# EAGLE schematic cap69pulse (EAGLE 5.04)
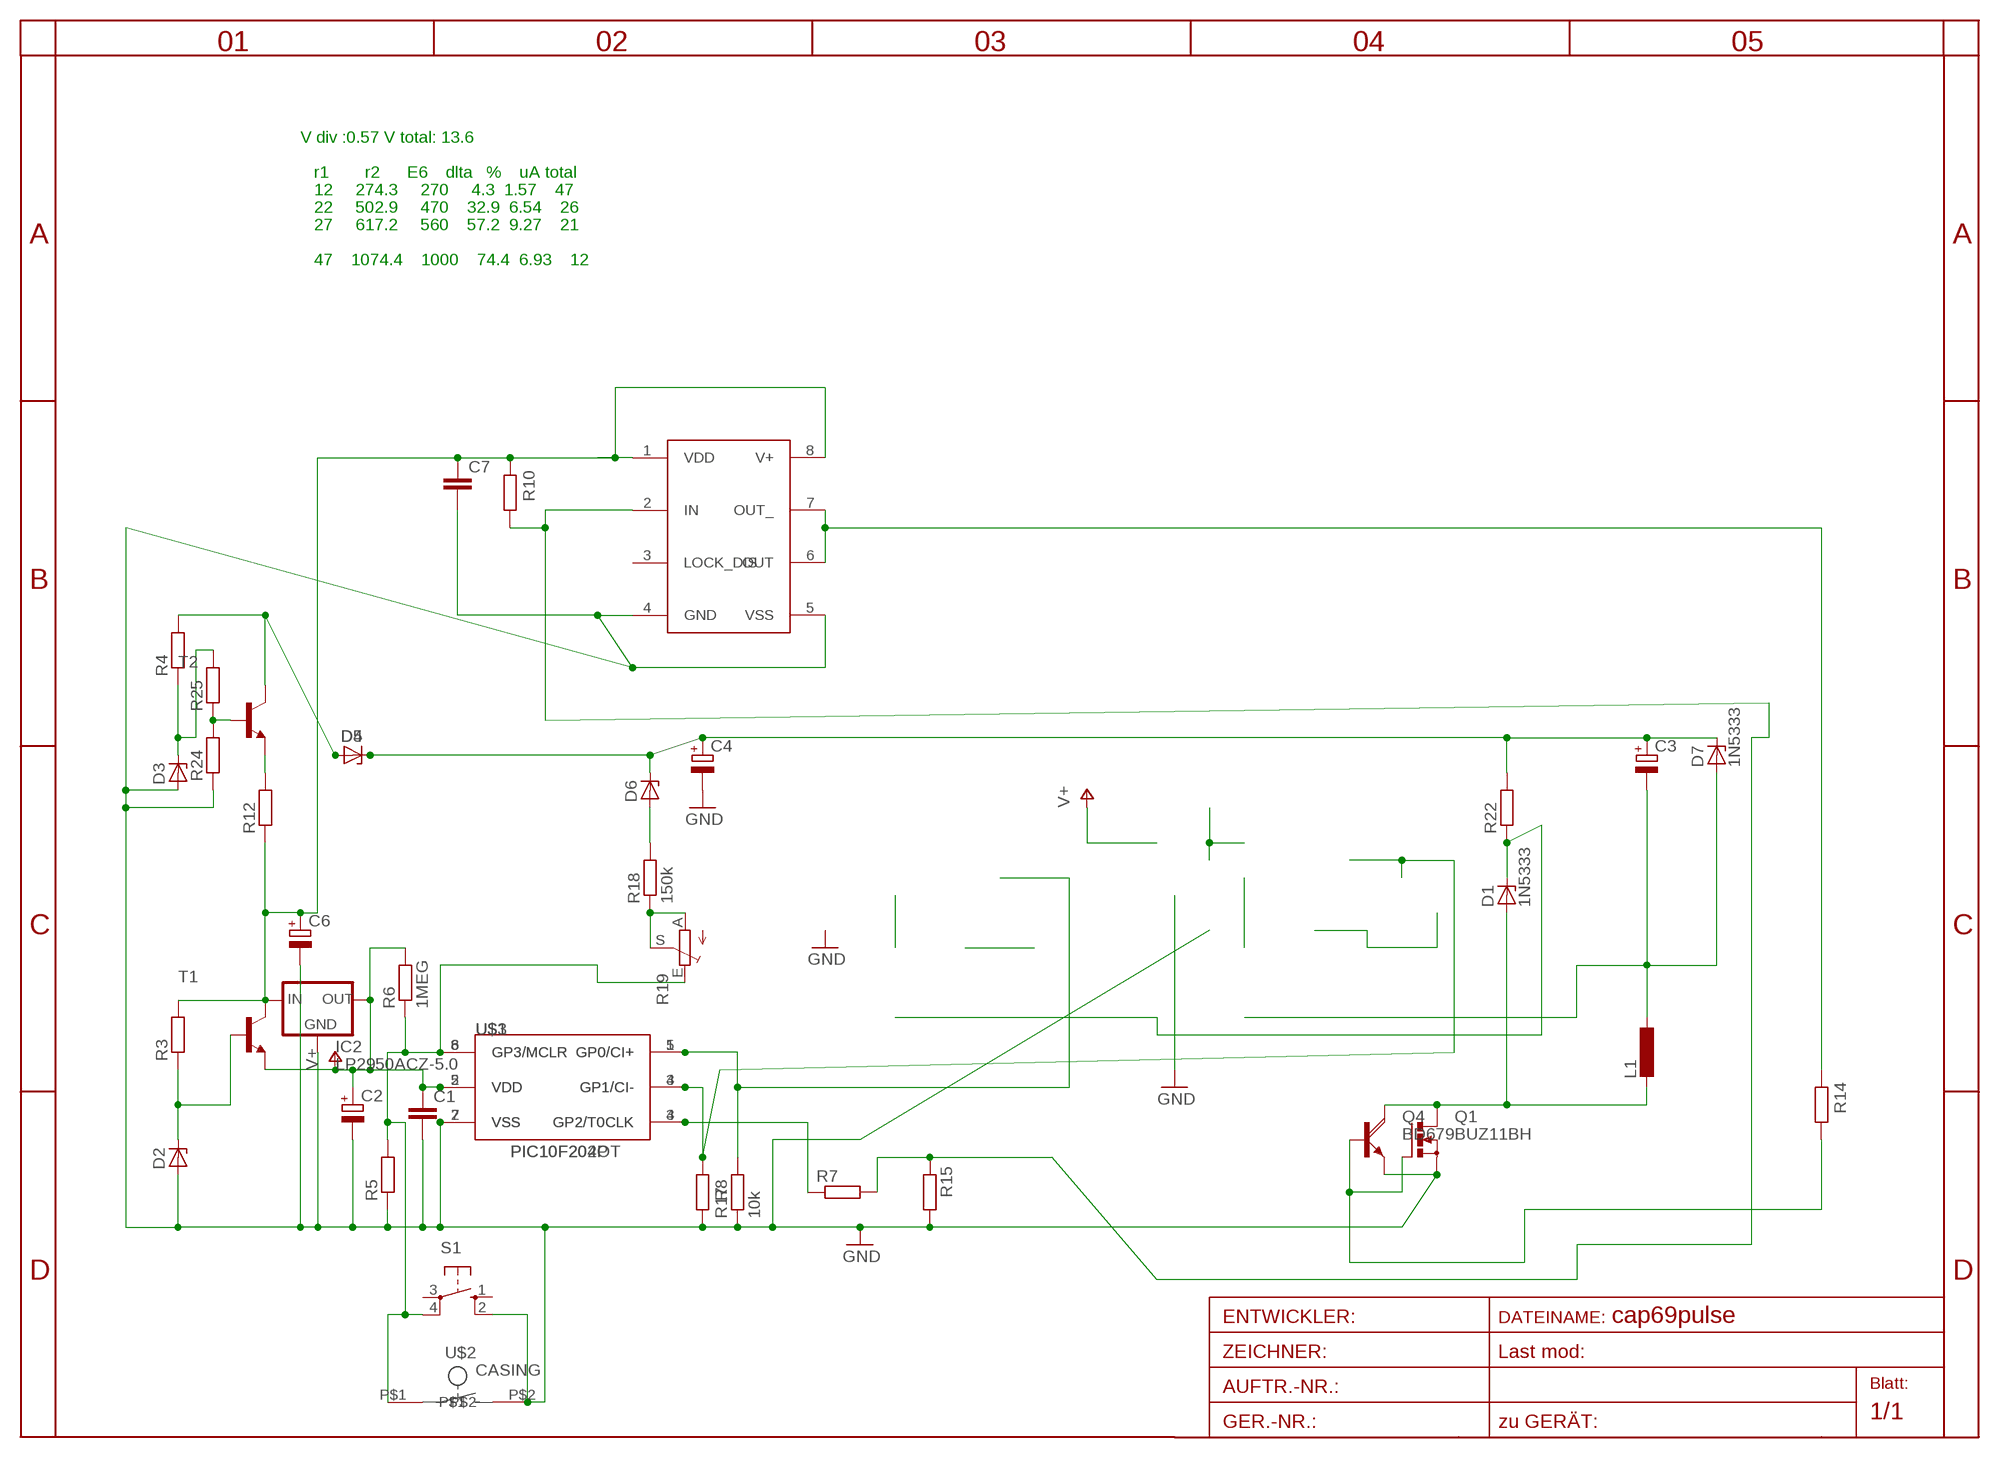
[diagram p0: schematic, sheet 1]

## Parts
C1  C-EUC1206  [C1206]
C2  CPOL-EUSANYO_SMD_E12  [SANYO-OSCON_SMD_E12]
C3  CPOL-EUE5-8.5  [E5-8,5]
C4  CPOL-EUE5-8.5  [E5-8,5]
C6  CPOL-EUSANYO_SMD_E12  [SANYO-OSCON_SMD_E12]
C7  C-EUC1206  [C1206]
D1  1N5333  [C1702-15]
D2  ZENER-DIODESOT23  [SOT23]
D3  ZENER-DIODESMB  [SMB]
D4  ZENER-DIODESMB  [SMB]
D5  ZENER-DIODESMB  [SMB]
D6  ZENER-DIODESMB  [SMB]
D7  1N5333  [C1702-15]
IC2  LP2950ACZ-5.0  [TO92]
IC3  TC4432X  [SO-08]
L1  L-EU2200-15.24  [2200-15.24]
Q1  BUZ11BH  [TO220BH]
Q4  BD679  [TO126AV]
R3  R-EU_R0805  [R0805]
R4  R-EU_R0805  [R0805]
R5  R-EU_R0805  [R0805]
R6  1MEG  R-EU_R1206  [R1206]
R7  R-EU_R0805  [R0805]
R8  R-EU_R0805  [R0805]
R10  R-EU_R0805  [R0805]
R12  R-EU_R0805  [R0805]
R14  R-EU_0207/10  [0207/10]
R15  R-EU_R0805  [R0805]
R17  10k  R-EU_R0805  [R0805]
R18  150k  R-EU_R1206  [R1206]
R19  TRIM_EU-CA6V  [CA6V]
R22  R-EU_0309/12  [0309/12]
R24  R-EU_R0805  [R0805]
R25  R-EU_R0805  [R0805]
S1  10-XX  [B3F-10XX]
T1  BC846BLT1-NPN-SOT23-BEC  [SOT23-BEC]
T2  BC846BLT1-NPN-SOT23-BEC  [SOT23-BEC]
U$1  PIC10F202OT  [SOT23-6]
U$2  CASING  [CASING]
U$3  PIC10F204P  [DIL8]

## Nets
BB: IC3.2(IN) R7.2 R10.1 R15.1
GATE: Q1.G Q4.B R14.1
GND: C1.2 C2.- C4.- C6.- C7.2 D2.1(A) D3.A IC2.2(GND) IC3.4(GND) IC3.5(VSS) Q1.S Q4.E R5.1 R8.1 R15.2 R17.1 R24.1 S1.2(S1) U$1.2(VSS) U$2.P$2 U$3.7(VSS)
HOT2: D1.C R22.1
HOTSPOT: D1.A L1.2 Q1.D Q4.C
N$2: R8.2 U$1.3(GP1/CI-) U$3.4(GP1/CI-)
N$6: D2.3(C) R3.1 T1.B
N$7: R5.2 R6.1 R19.E S1.4(P1) U$1.6(GP3/MCLR) U$2.P$1 U$3.8(GP3/MCLR)
N$9: R7.1 U$1.4(GP2/T0CLK) U$3.3(GP2/T0CLK)
N$10: R24.2 R25.1 T2.B
N$11: IC3.6(OUT) IC3.7(OUT_) R14.2
N$12: D3.C R4.1 R25.2
N$13: R18.1 R19.A R19.S
N$14: R17.2 U$1.1(GP0/CI+) U$3.5(GP0/CI+)
N$21: D4.A D5.A R4.2 T2.C
N$22: R12.2 T2.E
N$23: D6.A R18.2
V60: C3.+ C4.+ D4.C D5.C D6.C D7.C R22.2
V+: C1.1 C2.+ IC2.1(OUT) R6.2 T1.E U$1.5(VDD) U$3.2(VDD)
VCC: C6.+ C7.1 IC2.3(IN) IC3.1(VDD) IC3.8(V+) R3.2 R10.2 R12.1 T1.C
VOUT: C3.- D7.A L1.1
Unconnected: IC3.3(LOCK_DIS) S1.1(S) S1.3(P)

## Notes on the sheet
- V div :0.57 V total: 13.6
- r1        r2      E6    dlta   %    uA total
- 12     274.3     270     4.3  1.57    47
- 22     502.9     470    32.9  6.54    26
- 27     617.2     560    57.2  9.27    21
- 47    1074.4    1000    74.4  6.93    12

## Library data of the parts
C1 C7 = rcl:C-EU: CAPACITOR, European symbol
C2-C4 C6 = rcl:CPOL-EU: POLARIZED CAPACITOR, European symbol
D1 D7 = diode-1:1N5333: Z DIODE
D2-D6 = diode-1:ZENER-DIODE: Z-Diode
IC2 = v-reg:LP2950?*: Source: http://cache.national.com/ds/LP/LP2950.pdf
IC3 = microchip:TC4432
L1 = rcl:L-EU: INDUCTOR, European symbol
Q1 = transistor-power:BUZ11: N-CHANNEL MOS FET
Q4 = transistor-power:BD679: NPN DARLINGTON TRANSISTOR
R3-R6 R8 R10 R12 R14 R15 R24 R25 = rcl:R-EU_: RESISTOR, European symbol
R7 R17 R18 R22 = rcl-2:R-EU_: RESISTOR, European symbol
R19 = pot:TRIM_EU-: POTENTIOMETER
S1 = switch-omron:10-XX: OMRON SWITCH
T1 T2 = transistor-neu-to92:*-NPN-: NPN Transistror
U$1 U$3 = microchip-5:PIC10F2*: uPC nW 0,25/0,5k Program Flash memory Comparator
U$2 = button:CASING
